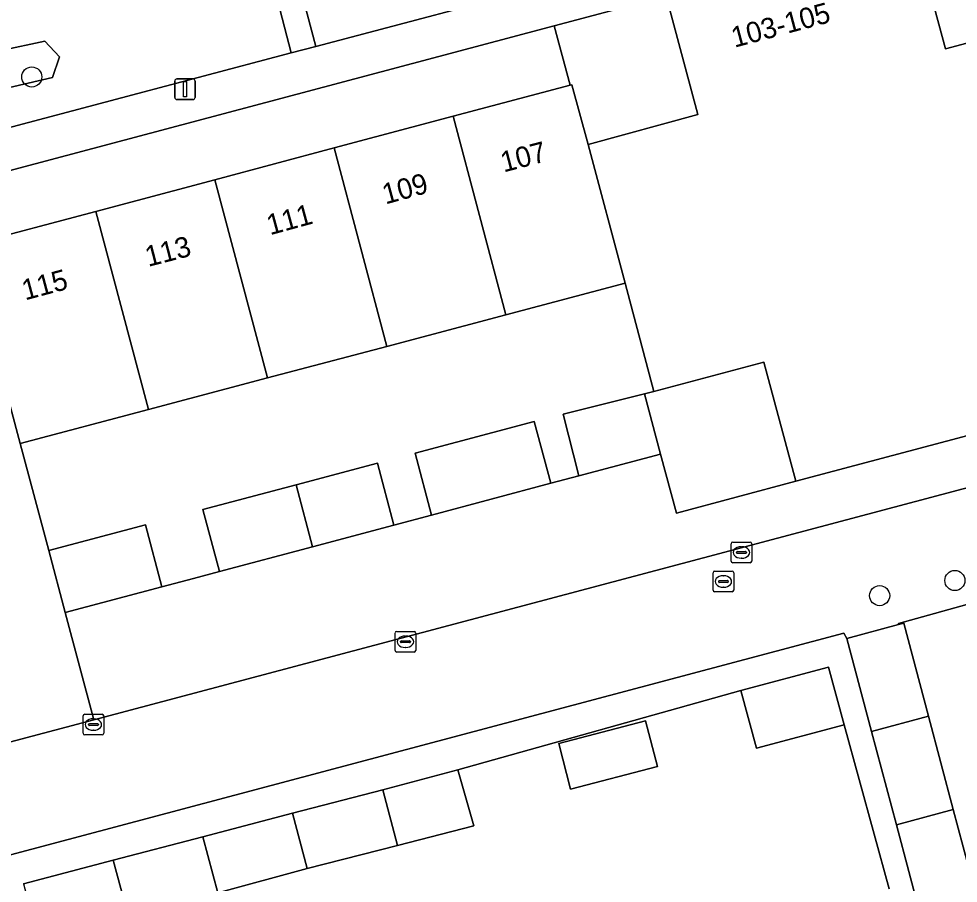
# Model space of a CAD drawing. Extents: x 162542 to 163147, y 380779 to 381521.
# Drawn here: x 162861.43 to 162907.17, y 381110.8 to 381152.86 of the extents above; entities that cross this region are included whole.
import ezdxf

# ---------------------------------------------------------------- set-up
doc = ezdxf.new("R2010")
doc.units = 0
for name, color, linetype in [('IMGEO_Boom', 7, 'Continuous'), ('IMGEO_Erf', 7, 'Continuous'), ('IMGEO_Groenvoorziening', 7, 'Continuous'), ('IMGEO_Kolk', 7, 'Continuous'), ('IMGEO_Lichtmast', 7, 'Continuous'), ('IMGEO_Muur', 7, 'Continuous'), ('IMGEO_Pand', 7, 'Continuous'), ('IMGEO_Pand_nummerreeks', 7, 'Continuous'), ('IMGEO_Parkeervlak_open', 7, 'Continuous'), ('IMGEO_Rijbaan_lokaal_open', 7, 'Continuous'), ('IMGEO_Rioolput', 7, 'Continuous'), ('IMGEO_Voetpad_open', 7, 'Continuous')]:
    doc.layers.add(name, color=color, linetype=linetype)

msp = doc.modelspace()

# ---------------------------------------------------------------- linework, layer by layer
at = {"layer": 'IMGEO_Boom'}
for centre in [(162862.066, 381150.034), (162907.004, 381125.529), (162903.342, 381124.791)]:
    msp.add_circle(centre, 0.489, dxfattribs=at)
at = {"layer": 'IMGEO_Erf'}
for points in [[(162904.989, 381157.182), (162906.54, 381151.404), (162912.337, 381152.94), (162910.777, 381158.734)], [(162887.505, 381152.528), (162888.27, 381149.632), (162888.364, 381149.657), (162889.15, 381146.754), (162894.491, 381148.211), (162892.949, 381153.986)], [(162887.942, 381133.626), (162891.901, 381134.613), (162892.347, 381134.732), (162890.948, 381139.991), (162885.149, 381138.456), (162879.349, 381136.921), (162873.548, 381135.386), (162867.747, 381133.851), (162861.5, 381132.198), (162862.89, 381126.986), (162867.603, 381128.24), (162868.405, 381125.225), (162869.933, 381125.631), (162871.204, 381125.969), (162870.402, 381128.984), (162874.93, 381130.189), (162878.894, 381131.243), (162879.696, 381128.228), (162881.531, 381128.716), (162880.729, 381131.731), (162886.527, 381133.273), (162887.329, 381130.258), (162888.691, 381130.62)], [(162899.268, 381130.359), (162897.698, 381136.153), (162892.347, 381134.732), (162891.901, 381134.613), (162892.676, 381131.68), (162893.46, 381128.813)], [(162887.719, 381117.591), (162891.943, 381118.698), (162892.524, 381116.476), (162888.294, 381115.37)]]:
    msp.add_lwpolyline(points, close=True, dxfattribs=at)
for points in [[(162912.087, 381125.607), (162904.26, 381123.431), (162904.267, 381123.387), (162904.512, 381123.452), (162905.717, 381118.928), (162906.926, 381114.388), (162908.136, 381109.847)], [(162903.813, 381110.528), (162901.61, 381118.51), (162897.339, 381117.369), (162896.588, 381120.178), (162882.812, 381116.307), (162883.589, 381113.582), (162879.878, 381112.64), (162875.481, 381111.506), (162871.121, 381110.329)]]:
    msp.add_lwpolyline(points, dxfattribs=at)
at = {"layer": 'IMGEO_Groenvoorziening'}
for points in [[(162885.815, 381160.368), (162885.803, 381160.365), (162874.356, 381157.34), (162875.889, 381151.523), (162887.685, 381154.645)], [(162873.192, 381157.033), (162854.959, 381152.215), (162855.121, 381151.63), (162858.584, 381150.843), (162860.575, 381151.323), (162862.708, 381151.781), (162863.421, 381151.008), (162863.083, 381150.009), (162856.023, 381148.37), (162856.566, 381146.408), (162874.69, 381151.205)], [(162855.121, 381151.63), (162856.023, 381148.37), (162863.083, 381150.009), (162863.421, 381151.008), (162862.708, 381151.781), (162860.575, 381151.323), (162858.584, 381150.843)]]:
    msp.add_lwpolyline(points, close=True, dxfattribs=at)
at = {"layer": 'IMGEO_Kolk'}
for p, q in [((162896.113, 381126.468), (162896.113, 381127.32)), ((162896.188, 381127.394), (162897.04, 381127.394)), ((162897.114, 381127.32), (162897.114, 381126.468)), ((162896.372, 381126.888), (162896.372, 381126.9)), ((162896.81, 381126.851), (162896.412, 381126.851)), ((162896.415, 381126.937), (162896.813, 381126.937)), ((162896.601, 381127.174), (162896.626, 381127.174)), ((162896.856, 381126.9), (162896.856, 381126.888)), ((162897.04, 381126.394), (162896.188, 381126.394)), ((162896.624, 381126.614), (162896.599, 381126.614)), ((162879.756, 381122.122), (162879.756, 381122.974)), ((162879.831, 381123.048), (162880.683, 381123.048)), ((162880.244, 381122.828), (162880.269, 381122.828)), ((162880.757, 381122.974), (162880.757, 381122.122)), ((162880.015, 381122.542), (162880.015, 381122.554)), ((162880.453, 381122.505), (162880.055, 381122.505)), ((162880.058, 381122.591), (162880.456, 381122.591)), ((162880.267, 381122.268), (162880.242, 381122.268)), ((162880.499, 381122.554), (162880.499, 381122.542)), ((162880.683, 381122.048), (162879.831, 381122.048)), ((162864.567, 381118.093), (162864.567, 381118.945)), ((162864.642, 381119.019), (162865.494, 381119.019)), ((162865.568, 381118.945), (162865.568, 381118.093)), ((162864.826, 381118.513), (162864.826, 381118.525)), ((162864.869, 381118.562), (162865.267, 381118.562)), ((162865.055, 381118.799), (162865.08, 381118.799)), ((162865.31, 381118.525), (162865.31, 381118.513)), ((162865.264, 381118.476), (162864.866, 381118.476)), ((162865.078, 381118.239), (162865.053, 381118.239)), ((162865.494, 381118.019), (162864.642, 381118.019))]:
    msp.add_line(p, q, dxfattribs=at)
for points in [[(162896.113, 381126.468), (162896.113, 381127.32)], [(162896.188, 381127.394), (162897.04, 381127.394)], [(162897.114, 381127.32), (162897.114, 381126.468)], [(162897.04, 381126.394), (162896.188, 381126.394)], [(162879.756, 381122.122), (162879.756, 381122.974)], [(162879.831, 381123.048), (162880.683, 381123.048)], [(162880.757, 381122.974), (162880.757, 381122.122)], [(162880.683, 381122.048), (162879.831, 381122.048)], [(162864.567, 381118.093), (162864.567, 381118.945)], [(162864.642, 381119.019), (162865.494, 381119.019)], [(162865.568, 381118.945), (162865.568, 381118.093)], [(162865.494, 381118.019), (162864.642, 381118.019)]]:
    msp.add_lwpolyline(points, dxfattribs=at)
for centre, radius, start, end in [((162896.19, 381127.318), 0.0765, 91.552, 178.448), ((162896.19, 381127.318), 0.0765, 91.552, 178.448), ((162897.038, 381127.318), 0.0765, 1.552, 88.448), ((162897.038, 381127.318), 0.0765, 1.552, 88.448), ((162896.412, 381126.897), 0.0403, 85.8775, 175.7526), ((162896.409, 381126.887), 0.0366, 178.938, 274.7102), ((162896.813, 381126.894), 0.043, 264.8664, 352.4533), ((162896.817, 381126.899), 0.0386, 1.7309, 96.639), ((162896.19, 381126.47), 0.0765, 181.552, 268.448), ((162896.19, 381126.47), 0.0765, 181.552, 268.448), ((162897.038, 381126.47), 0.0765, 271.552, 358.448), ((162897.038, 381126.47), 0.0765, 271.552, 358.448), ((162879.833, 381122.972), 0.0765, 91.552, 178.448), ((162879.833, 381122.972), 0.0765, 91.552, 178.448), ((162880.681, 381122.972), 0.0765, 1.552, 88.448), ((162880.681, 381122.972), 0.0765, 1.552, 88.448), ((162880.055, 381122.551), 0.0403, 85.8775, 175.7526), ((162880.052, 381122.541), 0.0366, 178.938, 274.7102), ((162880.456, 381122.548), 0.043, 264.8664, 352.4533), ((162880.46, 381122.553), 0.0386, 1.7309, 96.639), ((162879.833, 381122.124), 0.0765, 181.552, 268.448), ((162879.833, 381122.124), 0.0765, 181.552, 268.448), ((162880.681, 381122.124), 0.0765, 271.552, 358.448), ((162880.681, 381122.124), 0.0765, 271.552, 358.448), ((162864.644, 381118.943), 0.0765, 91.552, 178.448), ((162864.644, 381118.943), 0.0765, 91.552, 178.448), ((162865.492, 381118.943), 0.0765, 1.552, 88.448), ((162865.492, 381118.943), 0.0765, 1.552, 88.448), ((162864.866, 381118.522), 0.0403, 85.8775, 175.7526), ((162864.863, 381118.512), 0.0366, 178.938, 274.7102), ((162865.267, 381118.519), 0.043, 264.8664, 352.4533), ((162865.271, 381118.524), 0.0386, 1.7309, 96.639), ((162864.644, 381118.095), 0.0765, 181.552, 268.448), ((162864.644, 381118.095), 0.0765, 181.552, 268.448), ((162865.492, 381118.095), 0.0765, 271.552, 358.448), ((162865.492, 381118.095), 0.0765, 271.552, 358.448)]:
    msp.add_arc(centre, radius, start, end, dxfattribs=at)
for centre, major_axis, ratio, start_param, end_param in [((162896.6, 381126.894), (-0.387, 0.002), 0.722429, 4.712389, 7.853982), ((162896.625, 381126.894), (-0.39, 0.002), 0.717154, 1.570796, 4.712389), ((162880.243, 381122.548), (-0.387, 0.002), 0.722429, 4.712389, 7.853982), ((162880.268, 381122.548), (-0.39, 0.002), 0.717154, 1.570796, 4.712389), ((162865.054, 381118.519), (-0.387, 0.002), 0.722429, 4.712389, 7.853982), ((162865.079, 381118.519), (-0.39, 0.002), 0.717154, 1.570796, 4.712389)]:
    msp.add_ellipse(centre, major_axis=major_axis, ratio=ratio, start_param=start_param, end_param=end_param, dxfattribs=at)
at = {"layer": 'IMGEO_Lichtmast'}
for p, q in [((162869.03, 381149.035), (162869.03, 381149.835)), ((162869.03, 381149.835), (162869.03, 381149.035)), ((162869.13, 381149.935), (162869.92, 381149.935)), ((162869.92, 381149.935), (162869.13, 381149.935)), ((162870.02, 381149.835), (162870.02, 381149.035)), ((162870.02, 381149.035), (162870.02, 381149.835)), ((162869.92, 381148.935), (162869.13, 381148.935)), ((162869.13, 381148.935), (162869.92, 381148.935))]:
    msp.add_line(p, q, dxfattribs=at)
msp.add_lwpolyline([(162869.45, 381149.81), (162869.6, 381149.81), (162869.6, 381149.06), (162869.45, 381149.06), (162869.45, 381149.81)], dxfattribs=at)
for centre, start, end in [((162869.13, 381149.835), 90, 180), ((162869.13, 381149.835), 90, 180), ((162869.92, 381149.835), 0, 90), ((162869.92, 381149.835), 360, 90), ((162869.13, 381149.035), 180, 270), ((162869.13, 381149.035), 180, 270), ((162869.92, 381149.035), 270, 0), ((162869.92, 381149.035), 270, 0)]:
    msp.add_arc(centre, 0.1, start, end, dxfattribs=at)
at = {"layer": 'IMGEO_Muur'}
for points in [[(162887.505, 381152.528), (162892.949, 381153.986)], [(162888.27, 381149.632), (162887.505, 381152.528)], [(162861.5, 381132.198), (162862.89, 381126.986)], [(162892.676, 381131.68), (162893.46, 381128.813), (162899.268, 381130.359)], [(162912.087, 381125.607), (162904.26, 381123.431), (162904.267, 381123.387)]]:
    msp.add_lwpolyline(points, dxfattribs=at)
at = {"layer": 'IMGEO_Pand'}
for points in [[(162912.337, 381152.94), (162906.54, 381151.404), (162904.989, 381157.182), (162892.949, 381153.986), (162894.491, 381148.211), (162889.15, 381146.754), (162890.948, 381139.991), (162892.347, 381134.732), (162897.698, 381136.153), (162899.268, 381130.359), (162911.299, 381133.566), (162909.754, 381139.342), (162915.553, 381140.895)], [(162889.15, 381146.754), (162888.364, 381149.657), (162888.27, 381149.632), (162882.579, 381148.119), (162885.149, 381138.456), (162890.948, 381139.991)], [(162882.579, 381148.119), (162876.781, 381146.577), (162879.349, 381136.921), (162885.149, 381138.456)], [(162873.548, 381135.386), (162879.349, 381136.921), (162876.781, 381146.577), (162870.982, 381145.035)], [(162865.183, 381143.493), (162867.747, 381133.851), (162873.548, 381135.386), (162870.982, 381145.035)], [(162865.183, 381143.493), (162858.926, 381141.83), (162861.5, 381132.198), (162867.747, 381133.851)], [(162891.901, 381134.613), (162887.942, 381133.626), (162888.691, 381130.62), (162892.676, 381131.68)], [(162887.329, 381130.258), (162886.527, 381133.273), (162880.729, 381131.731), (162881.531, 381128.716)], [(162878.894, 381131.243), (162874.93, 381130.189), (162875.732, 381127.173), (162879.696, 381128.228)], [(162874.93, 381130.189), (162870.402, 381128.984), (162871.204, 381125.969), (162875.732, 381127.173)], [(162867.603, 381128.24), (162862.89, 381126.986), (162863.692, 381123.971), (162868.405, 381125.225)], [(162902.948, 381118.181), (162905.717, 381118.928), (162904.512, 381123.452), (162904.267, 381123.387), (162901.741, 381122.714)], [(162896.588, 381120.178), (162897.339, 381117.369), (162901.61, 381118.51), (162900.859, 381121.319)], [(162887.719, 381117.591), (162888.294, 381115.37), (162892.524, 381116.476), (162891.943, 381118.698)], [(162906.926, 381114.388), (162905.717, 381118.928), (162902.948, 381118.181), (162904.158, 381113.641)], [(162879.15, 381115.349), (162879.878, 381112.64), (162883.589, 381113.582), (162882.812, 381116.307)], [(162874.757, 381114.199), (162875.481, 381111.506), (162879.878, 381112.64), (162879.15, 381115.349)], [(162905.367, 381109.1), (162908.136, 381109.847), (162906.926, 381114.388), (162904.158, 381113.641)], [(162870.394, 381113.056), (162871.121, 381110.329), (162875.481, 381111.506), (162874.757, 381114.199)], [(162866.036, 381111.915), (162866.769, 381109.164), (162871.121, 381110.329), (162870.394, 381113.056)], [(162861.666, 381110.771), (162862.404, 381108), (162866.769, 381109.164), (162866.036, 381111.915)]]:
    msp.add_lwpolyline(points, close=True, dxfattribs=at)
at = {"layer": 'IMGEO_Parkeervlak_open'}
msp.add_lwpolyline([(162892.676, 381131.68), (162888.691, 381130.62), (162887.329, 381130.258), (162881.531, 381128.716), (162879.696, 381128.228), (162875.732, 381127.173), (162871.204, 381125.969), (162869.933, 381125.631), (162868.405, 381125.225), (162863.692, 381123.971), (162865.087, 381118.745), (162917.722, 381132.729), (162917.102, 381135.094), (162911.299, 381133.566), (162899.268, 381130.359), (162893.46, 381128.813)], close=True, dxfattribs=at)
at = {"layer": 'IMGEO_Rijbaan_lokaal_open'}
msp.add_lwpolyline([(162901.595, 381122.971), (162901.741, 381122.714), (162904.267, 381123.387), (162904.26, 381123.431), (162912.087, 381125.607), (162919.026, 381127.451), (162917.722, 381132.729), (162865.087, 381118.745), (162860.735, 381117.589), (162802.147, 381102.023), (162803.453, 381096.881), (162812.174, 381099.193), (162820.968, 381101.532), (162820.992, 381101.538)], close=True, dxfattribs=at)
at = {"layer": 'IMGEO_Rioolput'}
for p, q in [((162895.235, 381125.055), (162895.235, 381125.907)), ((162895.31, 381125.981), (162896.162, 381125.981)), ((162896.236, 381125.907), (162896.236, 381125.055)), ((162895.494, 381125.475), (162895.494, 381125.487)), ((162895.932, 381125.438), (162895.534, 381125.438)), ((162895.537, 381125.524), (162895.935, 381125.524)), ((162895.723, 381125.761), (162895.748, 381125.761)), ((162895.978, 381125.487), (162895.978, 381125.475)), ((162896.162, 381124.981), (162895.31, 381124.981)), ((162895.746, 381125.201), (162895.721, 381125.201))]:
    msp.add_line(p, q, dxfattribs=at)
for points in [[(162895.235, 381125.055), (162895.235, 381125.907)], [(162895.31, 381125.981), (162896.162, 381125.981)], [(162896.236, 381125.907), (162896.236, 381125.055)], [(162896.162, 381124.981), (162895.31, 381124.981)]]:
    msp.add_lwpolyline(points, dxfattribs=at)
for centre, radius, start, end in [((162895.312, 381125.905), 0.0765, 91.552, 178.448), ((162895.312, 381125.905), 0.0765, 91.552, 178.448), ((162896.16, 381125.905), 0.0765, 1.552, 88.448), ((162896.16, 381125.905), 0.0765, 1.552, 88.448), ((162895.534, 381125.484), 0.0403, 85.8775, 175.7526), ((162895.531, 381125.474), 0.0366, 178.938, 274.7102), ((162895.935, 381125.481), 0.043, 264.8664, 352.4533), ((162895.939, 381125.486), 0.0386, 1.7309, 96.639), ((162895.312, 381125.057), 0.0765, 181.552, 268.448), ((162895.312, 381125.057), 0.0765, 181.552, 268.448), ((162896.16, 381125.057), 0.0765, 271.552, 358.448), ((162896.16, 381125.057), 0.0765, 271.552, 358.448)]:
    msp.add_arc(centre, radius, start, end, dxfattribs=at)
for centre, major_axis, ratio, start_param, end_param in [((162895.722, 381125.481), (-0.387, 0.002), 0.722429, 4.712389, 7.853982), ((162895.747, 381125.481), (-0.39, 0.002), 0.717154, 1.570796, 4.712389)]:
    msp.add_ellipse(centre, major_axis=major_axis, ratio=ratio, start_param=start_param, end_param=end_param, dxfattribs=at)
at = {"layer": 'IMGEO_Voetpad_open'}
for points in [[(162873.192, 381157.033), (162874.69, 381151.205), (162875.889, 381151.523), (162874.356, 381157.34)], [(162858.926, 381141.83), (162865.183, 381143.493), (162870.982, 381145.035), (162876.781, 381146.577), (162882.579, 381148.119), (162888.27, 381149.632), (162887.505, 381152.528), (162858.133, 381144.726)], [(162858.926, 381141.83), (162858.133, 381144.726), (162853.786, 381143.563), (162854.582, 381140.682), (162857.156, 381131.038), (162858.533, 381125.84), (162859.337, 381122.826), (162860.735, 381117.589), (162865.087, 381118.745), (162863.692, 381123.971), (162862.89, 381126.986), (162861.5, 381132.198)]]:
    msp.add_lwpolyline(points, close=True, dxfattribs=at)
for points in [[(162887.685, 381154.645), (162875.889, 381151.523), (162874.69, 381151.205), (162856.566, 381146.408), (162854.578, 381145.881), (162836.301, 381141.008), (162834.855, 381140.622), (162827.907, 381138.769), (162824.718, 381137.919), (162823.599, 381137.62), (162818.27, 381136.199), (162807.632, 381133.362), (162805.687, 381132.844), (162798.503, 381130.928)], [(162801.2, 381129.568), (162807.214, 381131.172), (162813.229, 381132.776), (162818.672, 381134.227), (162853.786, 381143.563), (162858.133, 381144.726), (162887.505, 381152.528), (162892.949, 381153.986)], [(162905.367, 381109.1), (162904.158, 381113.641), (162902.948, 381118.181), (162901.741, 381122.714), (162901.595, 381122.971), (162820.992, 381101.538)], [(162861.666, 381110.771), (162866.036, 381111.915), (162870.394, 381113.056), (162874.757, 381114.199), (162879.15, 381115.349), (162882.812, 381116.307), (162896.588, 381120.178), (162900.859, 381121.319), (162901.61, 381118.51), (162903.813, 381110.528)]]:
    msp.add_lwpolyline(points, dxfattribs=at)

# ---------------------------------------------------------------- texts
at = {"layer": 'IMGEO_Pand_nummerreeks'}
for s, rotation, p in [('103-105', 14.9198, (162896.274, 381151.453)), ('107', 14.6505, (162885.039, 381145.384)), ('109', 15.3501, (162879.285, 381143.826)), ('111', 15.2551, (162873.663, 381142.327)), ('113', 14.4703, (162867.733, 381140.788)), ('115', 14.9314, (162861.74, 381139.157))]:
    msp.add_text(s, height=1, rotation=rotation, dxfattribs=at).set_placement(p)

doc.saveas('drawing.dxf')
